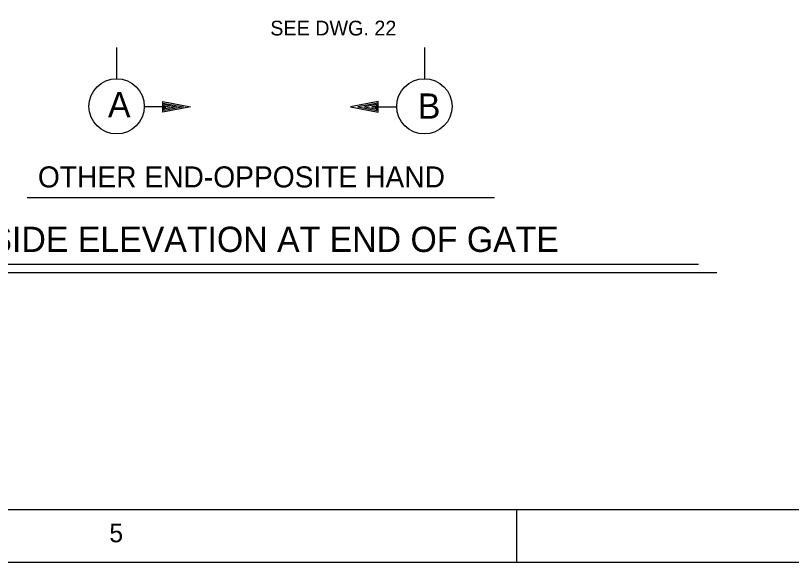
# Model space of a CAD drawing. Extents: x 4.9 to 31.6, y 3.9 to 22.6.
# Drawn here: x 7.739 to 12.647, y 3.926 to 7.389 of the extents above; entities that cross this region are included whole.
import ezdxf

# ---------------------------------------------------------------- set-up
doc = ezdxf.new("R2010")
doc.units = 0
for name, color, linetype in [('Level 1', 7, 'Continuous'), ('Level 3', 7, 'Continuous'), ('Level 50', 7, 'Continuous')]:
    doc.layers.add(name, color=color, linetype=linetype)

msp = doc.modelspace()

# ---------------------------------------------------------------- linework, layer by layer
at = {"layer": 'Level 1'}
msp.add_line((10.9069, 4.2594), (10.9069, 3.926), dxfattribs=at)
for points in [[(4.9069, 22.5927), (31.5735, 22.5927), (31.5735, 3.926), (4.9069, 3.926)], [(5.9069, 22.2594), (31.2402, 22.2594), (31.2402, 4.2594), (5.9069, 4.2594)]]:
    msp.add_lwpolyline(points, close=True, dxfattribs=at)
at = {"layer": 'Level 3'}
for p, q in [((8.3785, 7.1869), (8.3785, 6.9854)), ((10.3252, 7.1869), (10.3252, 6.9854)), ((8.6701, 6.8107), (8.5535, 6.8107)), ((10.0336, 6.8107), (10.1502, 6.8107))]:
    msp.add_line(p, q, dxfattribs=at)
for points in [[(8.6701, 6.8352), (8.6701, 6.8439), (8.8451, 6.8107), (8.6701, 6.778), (8.6701, 6.8352), (8.8005, 6.8113), (8.6785, 6.7879), (8.6785, 6.8256), (8.7565, 6.8113), (8.6867, 6.7982), (8.6867, 6.8157), (8.7118, 6.8113), (8.6952, 6.8081)], [(10.0336, 6.8352), (10.0336, 6.8439), (9.8586, 6.8107), (10.0336, 6.778), (10.0336, 6.8352), (9.9032, 6.8113), (10.0251, 6.7879), (10.0251, 6.8256), (9.9472, 6.8113), (10.017, 6.7982), (10.017, 6.8157), (9.9919, 6.8113), (10.0085, 6.8081)]]:
    msp.add_lwpolyline(points, dxfattribs=at)
for centre in [(8.3784, 6.8141), (10.3253, 6.8141)]:
    msp.add_circle(centre, 0.175, dxfattribs=at)
at = {"layer": 'Level 50'}
for p, q in [((7.8124, 6.2376), (10.768, 6.2376)), ((6.6215, 5.8149), (12.0587, 5.8149)), ((6.5323, 5.7631), (12.1748, 5.7631))]:
    msp.add_line(p, q, dxfattribs=at)

# ---------------------------------------------------------------- texts
at = {"layer": 'Level 1'}
msp.add_text('5', height=0.1168, dxfattribs=at).set_placement((8.3325, 4.0541))
at = {"layer": 'Level 50'}
for s, height, p in [('SEE DWG. 22', 0.093292, (9.3504, 7.2629)), ('A', 0.16, (8.3237, 6.7447)), ('B', 0.16, (10.2837, 6.7358)), ('OTHER END-OPPOSITE HAND', 0.133292, (7.8805, 6.3006)), ('FLOOD SIDE ELEVATION AT END OF GATE', 0.16, (6.7776, 5.8921))]:
    msp.add_text(s, height=height, dxfattribs=at).set_placement(p)

doc.saveas('drawing.dxf')
